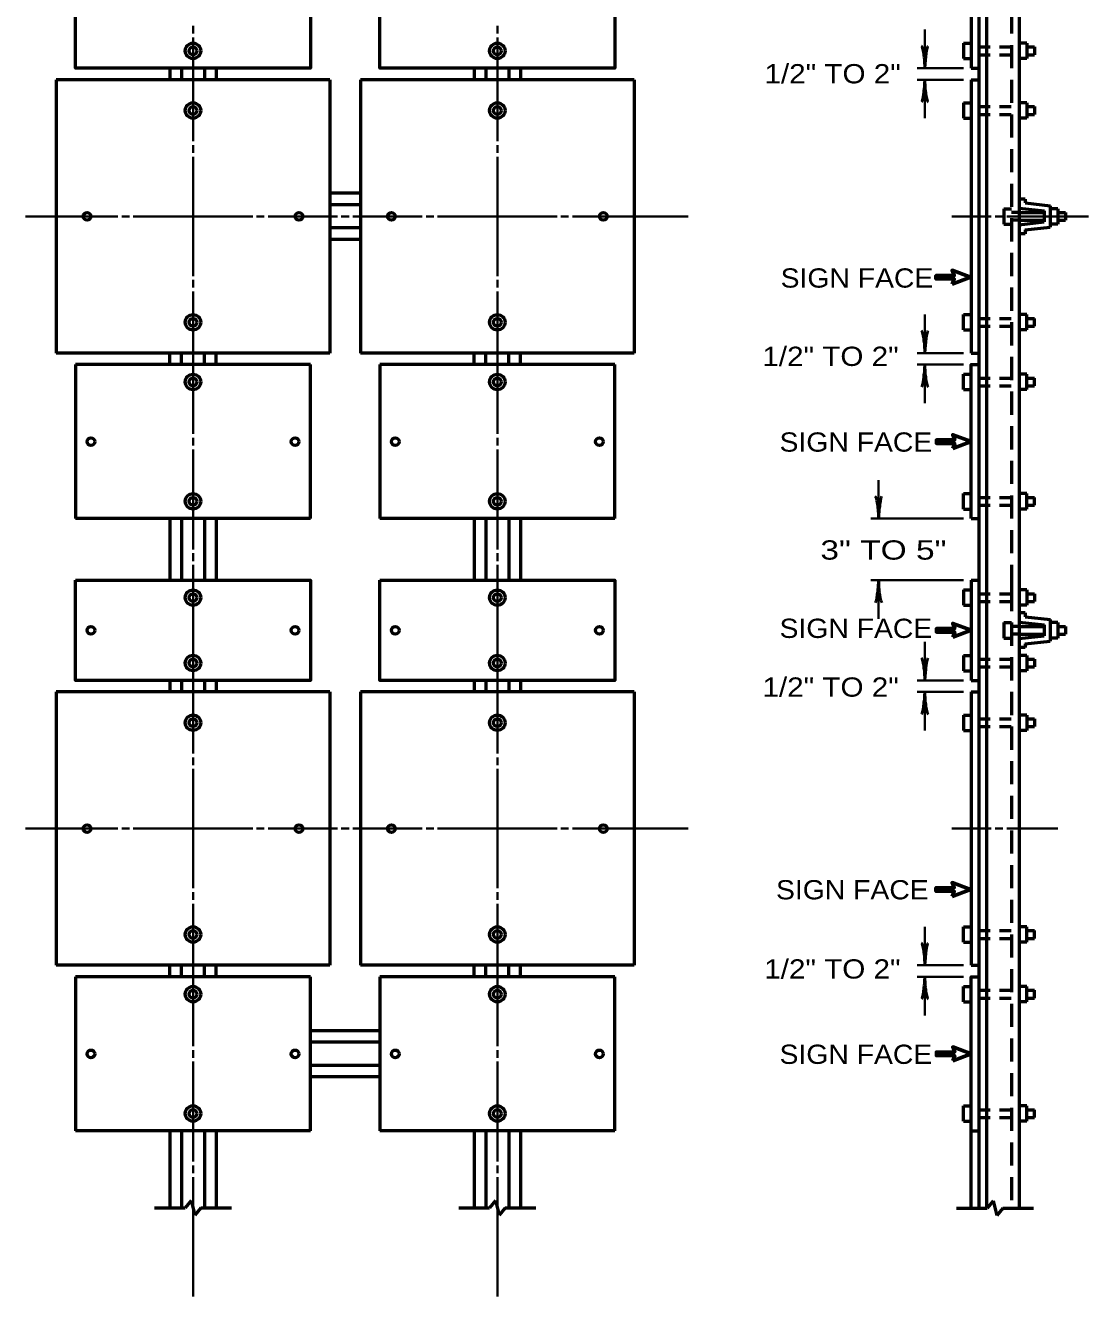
# Model space of a CAD drawing. Extents: x -45 to 635, y -382 to 59.
# Drawn here: x 313.3 to 451.3, y -273.6 to -108.5 of the extents above; entities that cross this region are included whole.
import ezdxf
from ezdxf.enums import TextEntityAlignment as Align

# ---------------------------------------------------------------- set-up
doc = ezdxf.new("R2010")
doc.units = 0
doc.linetypes.add('MEDIUM_DASHED', pattern=[4.5, 3, -1.5])
doc.linetypes.add('SHORT_DASHED', pattern=[2.7, 1.5, -1.2])
doc.layers.add('1', color=7, linetype='Continuous', lineweight=53)

msp = doc.modelspace()

# ---------------------------------------------------------------- linework, layer by layer
at = {"layer": '1'}
for p, q in [((436.035, -101.09), (436.035, -114.09)), ((438.035, -102.09), (438.035, -181.59)), ((442.285, -102.09), (442.285, -181.59)), ((435.035, -110.84), (435.035, -112.84)), ((435.035, -110.84), (436.035, -110.84)), ((443.285, -110.84), (442.285, -110.84)), ((443.285, -110.84), (443.285, -112.84)), ((443.285, -111.34), (444.285, -111.34)), ((444.285, -111.34), (444.285, -112.34)), ((435.035, -112.84), (436.035, -112.84)), ((443.285, -112.84), (442.285, -112.84)), ((443.285, -112.34), (444.285, -112.34)), ((332.05, -114.09), (332.05, -115.59)), ((333.55, -114.09), (333.55, -115.59)), ((336.55, -114.09), (336.55, -115.59)), ((338.05, -114.09), (338.05, -115.59)), ((371.55, -114.09), (371.55, -115.59)), ((373.05, -114.09), (373.05, -115.59)), ((376.05, -114.09), (376.05, -115.59)), ((377.55, -114.09), (377.55, -115.59)), ((436.035, -114.09), (437.035, -114.09)), ((352.8, -115.59), (317.3, -115.59)), ((317.3, -115.59), (317.3, -151.09)), ((352.8, -115.59), (352.8, -151.09)), ((392.3, -115.59), (356.8, -115.59)), ((356.8, -115.59), (356.8, -151.09)), ((392.3, -115.59), (392.3, -151.09)), ((436.035, -115.59), (436.035, -151.09)), ((436.035, -115.59), (437.035, -115.59)), ((435.035, -118.59), (435.035, -120.59)), ((435.035, -118.59), (436.035, -118.59)), ((443.285, -118.59), (442.285, -118.59)), ((443.285, -118.59), (443.285, -120.59)), ((443.285, -119.09), (444.285, -119.09)), ((443.285, -120.09), (444.285, -120.09)), ((444.285, -119.09), (444.285, -120.09)), ((435.035, -120.59), (436.035, -120.59)), ((443.285, -120.59), (442.285, -120.59)), ((356.8, -130.34), (352.8, -130.34)), ((356.8, -131.84), (352.8, -131.84)), ((443.035, -131.09), (442.285, -131.09)), ((443.035, -131.09), (443.035, -131.59)), ((443.035, -131.59), (446.285, -131.951)), ((446.285, -131.951), (446.285, -134.729)), ((440.285, -132.34), (440.285, -134.34)), ((440.285, -132.34), (441.285, -132.34)), ((442.285, -132.261), (445.535, -132.622)), ((442.285, -132.84), (445.535, -132.84)), ((445.535, -132.622), (445.535, -134.058)), ((447.285, -132.34), (446.285, -132.34)), ((447.285, -132.34), (447.285, -134.34)), ((447.285, -132.84), (448.285, -132.84)), ((448.285, -132.84), (448.285, -133.84)), ((356.8, -134.84), (352.8, -134.84)), ((440.285, -134.34), (441.285, -134.34)), ((442.285, -133.84), (445.535, -133.84)), ((442.285, -134.419), (445.535, -134.058)), ((443.035, -135.09), (446.285, -134.729)), ((443.035, -135.09), (443.035, -135.59)), ((447.285, -134.34), (446.285, -134.34)), ((447.285, -133.84), (448.285, -133.84)), ((356.8, -136.34), (352.8, -136.34)), ((443.035, -135.59), (442.285, -135.59)), ((435.035, -148.09), (435.035, -146.09)), ((435.035, -146.09), (436.035, -146.09)), ((443.285, -146.09), (442.285, -146.09)), ((443.285, -148.09), (443.285, -146.09)), ((443.285, -146.59), (444.285, -146.59)), ((444.285, -147.59), (444.285, -146.59)), ((435.035, -148.09), (436.035, -148.09)), ((443.285, -148.09), (442.285, -148.09)), ((443.285, -147.59), (444.285, -147.59)), ((352.8, -151.09), (317.3, -151.09)), ((332.05, -152.59), (332.05, -151.09)), ((333.55, -152.59), (333.55, -151.09)), ((336.55, -152.59), (336.55, -151.09)), ((338.05, -152.59), (338.05, -151.09)), ((392.3, -151.09), (356.8, -151.09)), ((371.55, -152.59), (371.55, -151.09)), ((373.05, -152.59), (373.05, -151.09)), ((376.05, -152.59), (376.05, -151.09)), ((377.55, -152.59), (377.55, -151.09)), ((436.035, -151.09), (437.035, -151.09)), ((350.3, -152.59), (319.8, -152.59)), ((319.8, -152.59), (319.8, -172.59)), ((350.3, -172.59), (350.3, -152.59)), ((389.8, -152.59), (359.3, -152.59)), ((359.3, -152.59), (359.3, -172.59)), ((389.8, -172.59), (389.8, -152.59)), ((435.035, -155.84), (435.035, -153.84)), ((435.035, -153.84), (436.035, -153.84)), ((443.285, -153.84), (442.285, -153.84)), ((443.285, -155.84), (443.285, -153.84)), ((443.285, -154.34), (444.285, -154.34)), ((444.285, -155.34), (444.285, -154.34)), ((435.035, -155.84), (436.035, -155.84)), ((443.285, -155.84), (442.285, -155.84)), ((443.285, -155.34), (444.285, -155.34)), ((435.035, -171.34), (435.035, -169.34)), ((435.035, -169.34), (436.035, -169.34)), ((443.285, -169.34), (442.285, -169.34)), ((443.285, -171.34), (443.285, -169.34)), ((443.285, -169.84), (444.285, -169.84)), ((444.285, -170.84), (444.285, -169.84)), ((435.035, -171.34), (436.035, -171.34)), ((443.285, -171.34), (442.285, -171.34)), ((443.285, -170.84), (444.285, -170.84)), ((350.3, -172.59), (319.8, -172.59)), ((332.05, -172.59), (332.05, -180.59)), ((333.55, -172.59), (333.55, -180.59)), ((336.55, -172.59), (336.55, -180.59)), ((338.05, -172.59), (338.05, -180.59)), ((389.8, -172.59), (359.3, -172.59)), ((371.55, -172.59), (371.55, -180.59)), ((373.05, -172.59), (373.05, -180.59)), ((376.05, -172.59), (376.05, -180.59)), ((377.55, -172.59), (377.55, -180.59)), ((436.035, -172.59), (437.035, -172.59)), ((436.035, -180.59), (436.035, -193.59)), ((436.035, -180.59), (437.035, -180.59)), ((435.035, -181.84), (435.035, -183.84)), ((435.035, -181.84), (436.035, -181.84)), ((438.035, -181.59), (438.035, -262.11)), ((442.285, -181.59), (442.285, -262.11)), ((443.285, -181.84), (442.285, -181.84)), ((443.285, -181.84), (443.285, -183.84)), ((443.285, -182.34), (444.285, -182.34)), ((444.285, -182.34), (444.285, -183.34)), ((435.035, -183.84), (436.035, -183.84)), ((443.285, -183.84), (442.285, -183.84)), ((443.035, -184.84), (442.285, -184.84)), ((443.035, -184.84), (443.035, -185.34)), ((443.285, -183.34), (444.285, -183.34)), ((440.285, -186.09), (440.285, -188.09)), ((440.285, -186.09), (441.285, -186.09)), ((442.285, -186.011), (445.535, -186.372)), ((443.035, -185.34), (446.285, -185.701)), ((445.535, -186.372), (445.535, -187.808)), ((446.285, -185.701), (446.285, -188.479)), ((447.285, -186.09), (446.285, -186.09)), ((447.285, -186.09), (447.285, -188.09)), ((440.285, -188.09), (441.285, -188.09)), ((442.285, -186.59), (445.535, -186.59)), ((442.285, -187.59), (445.535, -187.59)), ((442.285, -188.169), (445.535, -187.808)), ((447.285, -188.09), (446.285, -188.09)), ((447.285, -186.59), (448.285, -186.59)), ((447.285, -187.59), (448.285, -187.59)), ((448.285, -186.59), (448.285, -187.59)), ((443.035, -189.34), (442.285, -189.34)), ((443.035, -188.84), (446.285, -188.479)), ((443.035, -188.84), (443.035, -189.34)), ((435.035, -190.34), (435.035, -192.34)), ((435.035, -190.34), (436.035, -190.34)), ((443.285, -190.34), (442.285, -190.34)), ((443.285, -190.34), (443.285, -192.34)), ((443.285, -190.84), (444.285, -190.84)), ((444.285, -190.84), (444.285, -191.84)), ((435.035, -192.34), (436.035, -192.34)), ((443.285, -192.34), (442.285, -192.34)), ((443.285, -191.84), (444.285, -191.84)), ((332.05, -193.59), (332.05, -195.09)), ((333.55, -193.59), (333.55, -195.09)), ((336.55, -193.59), (336.55, -195.09)), ((338.05, -193.59), (338.05, -195.09)), ((371.55, -193.59), (371.55, -195.09)), ((373.05, -193.59), (373.05, -195.09)), ((376.05, -193.59), (376.05, -195.09)), ((377.55, -193.59), (377.55, -195.09)), ((436.035, -193.59), (437.035, -193.59)), ((352.8, -195.09), (317.3, -195.09)), ((317.3, -195.09), (317.3, -230.59)), ((352.8, -195.09), (352.8, -230.59)), ((392.3, -195.09), (356.8, -195.09)), ((356.8, -195.09), (356.8, -230.59)), ((392.3, -195.09), (392.3, -230.59)), ((436.035, -195.09), (436.035, -230.59)), ((436.035, -195.09), (437.035, -195.09)), ((435.035, -198.09), (435.035, -200.09)), ((435.035, -198.09), (436.035, -198.09)), ((443.285, -198.09), (442.285, -198.09)), ((443.285, -198.09), (443.285, -200.09)), ((443.285, -198.59), (444.285, -198.59)), ((443.285, -199.59), (444.285, -199.59)), ((444.285, -198.59), (444.285, -199.59)), ((435.035, -200.09), (436.035, -200.09)), ((443.285, -200.09), (442.285, -200.09)), ((435.035, -227.59), (435.035, -225.59)), ((435.035, -225.59), (436.035, -225.59)), ((443.285, -225.59), (442.285, -225.59)), ((443.285, -227.59), (443.285, -225.59)), ((443.285, -226.09), (444.285, -226.09)), ((444.285, -227.09), (444.285, -226.09)), ((435.035, -227.59), (436.035, -227.59)), ((443.285, -227.59), (442.285, -227.59)), ((443.285, -227.09), (444.285, -227.09)), ((352.8, -230.59), (317.3, -230.59)), ((332.05, -232.09), (332.05, -230.59)), ((333.55, -232.09), (333.55, -230.59)), ((336.55, -232.09), (336.55, -230.59)), ((338.05, -232.09), (338.05, -230.59)), ((392.3, -230.59), (356.8, -230.59)), ((371.55, -232.09), (371.55, -230.59)), ((373.05, -232.09), (373.05, -230.59)), ((376.05, -232.09), (376.05, -230.59)), ((377.55, -232.09), (377.55, -230.59)), ((436.035, -230.59), (437.035, -230.59)), ((350.3, -232.09), (319.8, -232.09)), ((319.8, -232.09), (319.8, -252.09)), ((350.3, -252.09), (350.3, -232.09)), ((389.8, -232.09), (359.3, -232.09)), ((359.3, -232.09), (359.3, -252.09)), ((389.8, -252.09), (389.8, -232.09)), ((435.035, -235.34), (435.035, -233.34)), ((435.035, -233.34), (436.035, -233.34)), ((443.285, -233.34), (442.285, -233.34)), ((443.285, -235.34), (443.285, -233.34)), ((443.285, -233.84), (444.285, -233.84)), ((444.285, -234.84), (444.285, -233.84)), ((435.035, -235.34), (436.035, -235.34)), ((443.285, -235.34), (442.285, -235.34)), ((443.285, -234.84), (444.285, -234.84)), ((359.3, -239.09), (350.3, -239.09)), ((359.3, -240.59), (350.3, -240.59)), ((359.3, -243.59), (350.3, -243.59)), ((359.3, -245.09), (350.3, -245.09)), ((435.035, -250.84), (435.035, -248.84)), ((435.035, -248.84), (436.035, -248.84)), ((443.285, -248.84), (442.285, -248.84)), ((443.285, -250.84), (443.285, -248.84)), ((435.035, -250.84), (436.035, -250.84)), ((443.285, -250.84), (442.285, -250.84)), ((443.285, -249.34), (444.285, -249.34)), ((443.285, -250.34), (444.285, -250.34)), ((444.285, -250.34), (444.285, -249.34)), ((350.3, -252.09), (319.8, -252.09)), ((332.05, -252.09), (332.05, -262.09)), ((333.55, -252.09), (333.55, -262.09)), ((336.55, -252.09), (336.55, -262.09)), ((338.05, -252.09), (338.05, -262.09)), ((389.8, -252.09), (359.3, -252.09)), ((371.55, -252.09), (371.55, -262.09)), ((373.05, -252.09), (373.05, -262.09)), ((376.05, -252.09), (376.05, -262.09)), ((377.55, -252.09), (377.55, -262.09)), ((436.035, -252.09), (437.035, -252.09)), ((330.05, -262.09), (334.05, -262.09)), ((334.828, -261.116), (334.05, -262.09)), ((334.828, -261.116), (335.304, -263.022)), ((336.05, -262.09), (335.304, -263.022)), ((336.05, -262.09), (340.05, -262.09)), ((369.55, -262.09), (373.55, -262.09)), ((374.328, -261.116), (373.55, -262.09)), ((374.328, -261.116), (374.804, -263.022)), ((375.55, -262.09), (374.804, -263.022)), ((375.55, -262.09), (379.55, -262.09)), ((434.143, -262.131), (438.143, -262.131)), ((438.922, -261.157), (438.143, -262.131)), ((438.922, -261.157), (439.397, -263.063)), ((440.143, -262.131), (439.397, -263.063)), ((440.143, -262.131), (444.143, -262.131))]:
    msp.add_line(p, q, dxfattribs=at)
at = {"layer": '1', "linetype": 'MEDIUM_DASHED'}
for p, q in [((441.285, -102.09), (441.285, -181.59)), ((441.285, -181.59), (441.285, -262.11))]:
    msp.add_line(p, q, dxfattribs=at)
at = {"layer": '1', "lineweight": 35}
for p, q in [((335.05, -108.59), (335.05, -109.59)), ((374.55, -108.59), (374.55, -109.59)), ((335.05, -110.09), (335.05, -123.59)), ((374.55, -110.09), (374.55, -123.59)), ((430.035, -114.09), (430.035, -109.09)), ((435.035, -114.09), (429.035, -114.09)), ((435.035, -115.59), (429.035, -115.59)), ((430.035, -120.59), (430.035, -115.59)), ((335.05, -124.09), (335.05, -125.09)), ((374.55, -124.09), (374.55, -125.09)), ((335.05, -125.59), (335.05, -141.09)), ((374.55, -125.59), (374.55, -141.09)), ((313.3, -133.34), (325.3, -133.34)), ((325.8, -133.34), (326.8, -133.34)), ((327.3, -133.34), (342.8, -133.34)), ((343.3, -133.34), (344.3, -133.34)), ((344.8, -133.34), (352.8, -133.34)), ((352.8, -133.34), (353.8, -133.34)), ((354.3, -133.34), (355.3, -133.34)), ((355.8, -133.34), (356.8, -133.34)), ((356.8, -133.34), (364.8, -133.34)), ((357.919, -133.34), (359.8, -133.34)), ((365.3, -133.34), (366.3, -133.34)), ((366.8, -133.34), (382.3, -133.34)), ((382.8, -133.34), (383.8, -133.34)), ((384.3, -133.34), (399.3, -133.34)), ((433.535, -133.34), (438.66, -133.34)), ((439.16, -133.34), (440.16, -133.34)), ((440.66, -133.34), (444.285, -133.34)), ((451.285, -133.34), (444.285, -133.34)), ((335.05, -141.59), (335.05, -142.59)), ((374.55, -141.59), (374.55, -142.59)), ((335.05, -143.09), (335.05, -161.59)), ((374.55, -143.09), (374.55, -161.59)), ((430.035, -151.09), (430.035, -146.09)), ((435.035, -151.09), (429.035, -151.09)), ((435.035, -152.59), (429.035, -152.59)), ((430.035, -157.59), (430.035, -152.59)), ((335.05, -162.09), (335.05, -163.09)), ((374.55, -162.09), (374.55, -163.09)), ((335.05, -163.59), (335.05, -176.59)), ((374.55, -163.59), (374.55, -176.59)), ((424.035, -172.59), (424.035, -167.59)), ((435.035, -172.59), (423.035, -172.59)), ((335.05, -177.09), (335.05, -178.09)), ((374.55, -177.09), (374.55, -178.09)), ((335.05, -178.59), (335.05, -182.59)), ((374.55, -178.59), (374.55, -185.465)), ((435.035, -180.59), (423.035, -180.59)), ((424.035, -185.59), (424.035, -180.59)), ((335.05, -182.59), (335.05, -185.465)), ((335.05, -183.09), (335.05, -194.09)), ((374.55, -183.09), (374.55, -194.09)), ((335.05, -188.09), (335.05, -189.09)), ((374.55, -188.09), (374.55, -189.09)), ((335.05, -189.59), (335.05, -203.09)), ((374.55, -189.59), (374.55, -203.09)), ((430.035, -193.59), (430.035, -188.59)), ((435.035, -193.59), (429.035, -193.59)), ((435.035, -195.09), (429.035, -195.09)), ((430.035, -200.09), (430.035, -195.09)), ((335.05, -203.59), (335.05, -204.59)), ((374.55, -203.59), (374.55, -204.59)), ((335.05, -205.09), (335.05, -220.59)), ((374.55, -205.09), (374.55, -220.59)), ((313.3, -212.84), (325.3, -212.84)), ((325.8, -212.84), (326.8, -212.84)), ((327.3, -212.84), (342.8, -212.84)), ((343.3, -212.84), (344.3, -212.84)), ((344.8, -212.84), (352.8, -212.84)), ((352.8, -212.84), (353.8, -212.84)), ((354.3, -212.84), (355.3, -212.84)), ((355.8, -212.84), (356.8, -212.84)), ((356.8, -212.84), (364.8, -212.84)), ((357.919, -212.84), (359.8, -212.84)), ((365.3, -212.84), (366.3, -212.84)), ((366.8, -212.84), (382.3, -212.84)), ((382.8, -212.84), (383.8, -212.84)), ((384.3, -212.84), (399.3, -212.84)), ((433.535, -212.84), (438.66, -212.84)), ((439.16, -212.84), (440.16, -212.84)), ((440.66, -212.84), (447.285, -212.84)), ((335.05, -221.09), (335.05, -222.09)), ((374.55, -221.09), (374.55, -222.09)), ((335.05, -222.59), (335.05, -241.09)), ((374.55, -222.59), (374.55, -241.09)), ((430.035, -230.59), (430.035, -225.59)), ((435.035, -230.59), (429.035, -230.59)), ((435.035, -232.09), (429.035, -232.09)), ((430.035, -237.09), (430.035, -232.09)), ((335.05, -241.59), (335.05, -242.59)), ((374.55, -241.59), (374.55, -242.59)), ((335.05, -243.09), (335.05, -256.09)), ((374.55, -243.09), (374.55, -256.09)), ((335.05, -256.59), (335.05, -257.59)), ((374.55, -256.59), (374.55, -257.59)), ((335.05, -258.09), (335.05, -262.09)), ((374.55, -258.09), (374.55, -273.61)), ((335.05, -262.09), (335.05, -273.61))]:
    msp.add_line(p, q, dxfattribs=at)
at = {"layer": '1', "linetype": 'SHORT_DASHED'}
for p, q in [((437.035, -111.34), (442.285, -111.34)), ((437.035, -112.34), (442.285, -112.34)), ((437.035, -119.09), (442.285, -119.09)), ((437.035, -120.09), (442.285, -120.09)), ((442.285, -132.84), (441.285, -132.84)), ((442.285, -133.84), (441.285, -133.84)), ((437.035, -146.59), (442.285, -146.59)), ((437.035, -147.59), (442.285, -147.59)), ((437.035, -154.34), (442.285, -154.34)), ((437.035, -155.34), (442.285, -155.34)), ((437.035, -169.84), (442.285, -169.84)), ((437.035, -170.84), (442.285, -170.84)), ((437.035, -182.34), (442.285, -182.34)), ((437.035, -183.34), (442.285, -183.34)), ((442.285, -186.59), (441.285, -186.59)), ((442.285, -187.59), (441.285, -187.59)), ((437.035, -190.84), (442.285, -190.84)), ((437.035, -191.84), (442.285, -191.84)), ((437.035, -198.59), (442.285, -198.59)), ((437.035, -199.59), (442.285, -199.59)), ((437.035, -226.09), (442.285, -226.09)), ((437.035, -227.09), (442.285, -227.09)), ((437.035, -233.84), (442.285, -233.84)), ((437.035, -234.84), (442.285, -234.84)), ((437.035, -249.34), (442.285, -249.34)), ((437.035, -250.34), (442.285, -250.34))]:
    msp.add_line(p, q, dxfattribs=at)
at = {"layer": '1'}
for points in [[(319.8, -101.09), (350.3, -101.09), (350.3, -114.09), (319.8, -114.09)], [(359.3, -101.09), (389.8, -101.09), (389.8, -114.09), (359.3, -114.09)], [(319.8, -180.59), (350.3, -180.59), (350.3, -193.59), (319.8, -193.59)], [(359.3, -180.59), (389.8, -180.59), (389.8, -193.59), (359.3, -193.59)]]:
    msp.add_lwpolyline(points, close=True, dxfattribs=at)
for points in [[(437.035, -101.09), (437.035, -115.59), (437.035, -180.59)], [(436.035, -172.59), (436.035, -152.59), (437.035, -152.59)], [(437.035, -180.59), (437.035, -195.09), (437.035, -262.09)], [(436.035, -262.11), (436.035, -232.09), (437.035, -232.09)]]:
    msp.add_lwpolyline(points, dxfattribs=at)
at = {"layer": '1', "lineweight": 60}
for points in [[(433.581, -142.142), (435.966, -141.242), (433.581, -140.341), (433.851, -141.017), (431.466, -141.017), (431.466, -141.466), (433.851, -141.466)], [(433.65, -163.49), (436.035, -162.59), (433.65, -161.69), (433.92, -162.365), (431.535, -162.365), (431.535, -162.815), (433.92, -162.815)], [(433.65, -187.99), (436.035, -187.09), (433.65, -186.19), (433.92, -186.865), (431.535, -186.865), (431.535, -187.315), (433.92, -187.315)], [(433.581, -221.641), (435.966, -220.742), (433.581, -219.841), (433.851, -220.516), (431.466, -220.516), (431.466, -220.966), (433.851, -220.966)], [(433.65, -242.99), (436.035, -242.09), (433.65, -241.19), (433.92, -241.865), (431.535, -241.865), (431.535, -242.315), (433.92, -242.315)]]:
    msp.add_lwpolyline(points, close=True, dxfattribs=at)
at = {"layer": '1'}
for centre, radius in [((335.05, -111.84), 1), ((335.05, -111.84), 0.5), ((374.55, -111.84), 1), ((374.55, -111.84), 0.5), ((335.05, -119.59), 1), ((374.55, -119.59), 1), ((335.05, -119.59), 0.5), ((374.55, -119.59), 0.5), ((321.3, -133.34), 0.5), ((348.8, -133.34), 0.5), ((360.8, -133.34), 0.5), ((388.3, -133.34), 0.5), ((335.05, -147.09), 1), ((335.05, -147.09), 0.5), ((374.55, -147.09), 1), ((374.55, -147.09), 0.5), ((335.05, -154.84), 1), ((335.05, -154.84), 0.5), ((374.55, -154.84), 1), ((374.55, -154.84), 0.5), ((321.8, -162.59), 0.5), ((348.3, -162.59), 0.5), ((361.3, -162.59), 0.5), ((387.8, -162.59), 0.5), ((335.05, -170.34), 1), ((335.05, -170.34), 0.5), ((374.55, -170.34), 1), ((374.55, -170.34), 0.5), ((335.05, -182.84), 1), ((335.05, -182.84), 0.5), ((374.55, -182.84), 1), ((374.55, -182.84), 0.5), ((321.8, -187.09), 0.5), ((348.3, -187.09), 0.5), ((361.3, -187.09), 0.5), ((387.8, -187.09), 0.5), ((335.05, -191.34), 1), ((335.05, -191.34), 0.5), ((374.55, -191.34), 1), ((374.55, -191.34), 0.5), ((335.05, -199.09), 1), ((335.05, -199.09), 0.5), ((374.55, -199.09), 1), ((374.55, -199.09), 0.5), ((321.3, -212.84), 0.5), ((348.8, -212.84), 0.5), ((360.8, -212.84), 0.5), ((388.3, -212.84), 0.5), ((335.05, -226.59), 1), ((335.05, -226.59), 0.5), ((374.55, -226.59), 1), ((374.55, -226.59), 0.5), ((335.05, -234.34), 1), ((335.05, -234.34), 0.5), ((374.55, -234.34), 1), ((374.55, -234.34), 0.5), ((321.8, -242.09), 0.5), ((348.3, -242.09), 0.5), ((361.3, -242.09), 0.5), ((387.8, -242.09), 0.5), ((335.05, -249.84), 1), ((374.55, -249.84), 1), ((335.05, -249.84), 0.5), ((374.55, -249.84), 0.5)]:
    msp.add_circle(centre, radius, dxfattribs=at)
at = {"layer": '1', "lineweight": 40}
for centre, major_axis, ratio, start_param, end_param in [((429.758, -112.999), (0.156, -1.786), 0.122415, 0.8963533, 3.1415927), ((429.758, -112.999), (0.156, -1.786), 0.122415, 0.8963533, 3.1415927), ((430.246, -112.969), (-0.176, -1.756), 0.07063, 3.1407148, 5.41811), ((430.246, -112.969), (-0.176, -1.756), 0.07063, 3.1407148, 5.41811), ((429.823, -116.71), (0.176, 1.756), 0.07063, 3.1407148, 5.41811), ((430.311, -116.681), (-0.156, 1.786), 0.122415, 0.8963533, 3.1415927), ((429.758, -149.999), (0.156, -1.786), 0.122415, 0.8963533, 3.1415927), ((429.758, -149.999), (0.156, -1.786), 0.122415, 0.8963533, 3.1415927), ((430.246, -149.969), (-0.176, -1.756), 0.07063, 3.1407148, 5.41811), ((430.246, -149.969), (-0.176, -1.756), 0.07063, 3.1407148, 5.41811), ((429.823, -153.71), (0.176, 1.756), 0.07063, 3.1407148, 5.41811), ((430.311, -153.681), (-0.156, 1.786), 0.122415, 0.8963533, 3.1415927), ((423.758, -171.499), (0.156, -1.786), 0.122415, 0.8963533, 3.1415927), ((423.758, -171.499), (0.156, -1.786), 0.122415, 0.8963533, 3.1415927), ((424.246, -171.469), (-0.176, -1.756), 0.07063, 3.1407148, 5.41811), ((424.246, -171.469), (-0.176, -1.756), 0.07063, 3.1407148, 5.41811), ((423.823, -181.71), (0.176, 1.756), 0.07063, 3.1407148, 5.41811), ((423.823, -181.71), (0.176, 1.756), 0.07063, 3.1407148, 5.41811), ((424.311, -181.681), (-0.156, 1.786), 0.122415, 0.8963533, 3.1415927), ((424.311, -181.681), (-0.156, 1.786), 0.122415, 0.8963533, 3.1415927), ((429.758, -192.499), (0.156, -1.786), 0.122415, 0.8963533, 3.1415927), ((429.758, -192.499), (0.156, -1.786), 0.122415, 0.8963533, 3.1415927), ((430.246, -192.469), (-0.176, -1.756), 0.07063, 3.1407148, 5.41811), ((430.246, -192.469), (-0.176, -1.756), 0.07063, 3.1407148, 5.41811), ((429.823, -196.21), (0.176, 1.756), 0.07063, 3.1407148, 5.41811), ((430.311, -196.181), (-0.156, 1.786), 0.122415, 0.8963533, 3.1415927), ((429.758, -229.499), (0.156, -1.786), 0.122415, 0.8963533, 3.1415927), ((429.758, -229.499), (0.156, -1.786), 0.122415, 0.8963533, 3.1415927), ((430.246, -229.469), (-0.176, -1.756), 0.07063, 3.1407148, 5.41811), ((430.246, -229.469), (-0.176, -1.756), 0.07063, 3.1407148, 5.41811), ((429.823, -233.21), (0.176, 1.756), 0.07063, 3.1407148, 5.41811), ((429.823, -233.21), (0.176, 1.756), 0.07063, 3.1407148, 5.41811), ((430.311, -233.181), (-0.156, 1.786), 0.122415, 0.8963533, 3.1415927), ((430.311, -233.181), (-0.156, 1.786), 0.122415, 0.8963533, 3.1415927)]:
    msp.add_ellipse(centre, major_axis=major_axis, ratio=ratio, start_param=start_param, end_param=end_param, dxfattribs=at)

# ---------------------------------------------------------------- texts
at = {"layer": '1'}
for s, width, p in [('1/2" TO 2"', 1.15, (418.066, -116.063)), ('SIGN FACE', 1.1, (421.226, -142.588)), ('1/2" TO 2"', 1.15, (417.791, -152.758)), ('SIGN FACE', 1.1, (421.088, -163.891)), ('3" TO 5"', 1.3, (424.66, -177.91)), ('SIGN FACE', 1.1, (421.088, -188.08)), ('1/2" TO 2"', 1.15, (417.806, -195.707)), ('SIGN FACE', 1.1, (420.626, -222.031)), ('1/2" TO 2"', 1.15, (418.036, -232.314)), ('SIGN FACE', 1.1, (421.088, -243.395))]:
    msp.add_text(s, height=2.5, dxfattribs=dict(at, width=width)).set_placement(p, align=Align.CENTER)

doc.saveas('drawing.dxf')
